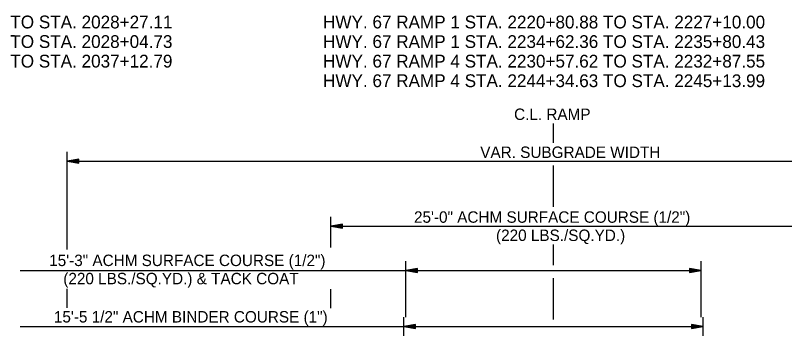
# Model space of a CAD drawing. Extents: x 1734743 to 1735935, y 759845 to 763831.
# Drawn here: x 1735729.77 to 1735769.47, y 762706.48 to 762722.65 of the extents above; entities that cross this region are included whole.
import ezdxf

# ---------------------------------------------------------------- set-up
doc = ezdxf.new("R2010")
doc.units = 0
doc.layers.add('19', color=7, linetype='Continuous')

msp = doc.modelspace()

# ---------------------------------------------------------------- linework, layer by layer
at = {"layer": '19'}
for p, q in [((1735757.547, 762716.063), (1735757.548, 762717.071)), ((1735732.446, 762710.573), (1735732.446, 762715.61)), ((1735733.046, 762715.23), (1735732.446, 762715.125)), ((1735732.446, 762715.125), (1735782.728, 762715.125)), ((1735732.446, 762715.125), (1735733.046, 762715.02)), ((1735733.046, 762715.175), (1735732.606, 762715.14)), ((1735732.606, 762715.11), (1735733.046, 762715.07)), ((1735733.046, 762715.02), (1735733.046, 762715.23)), ((1735757.548, 762712.763), (1735757.548, 762714.901)), ((1735746.047, 762710.67), (1735746.047, 762712.254)), ((1735746.647, 762711.874), (1735746.047, 762711.769)), ((1735746.647, 762711.819), (1735746.207, 762711.784)), ((1735746.647, 762711.664), (1735746.647, 762711.874)), ((1735746.047, 762711.769), (1735771.046, 762711.769)), ((1735746.047, 762711.769), (1735746.647, 762711.664)), ((1735746.207, 762711.754), (1735746.647, 762711.714)), ((1735757.548, 762709.759), (1735757.548, 762710.828)), ((1735749.92, 762707.074), (1735749.92, 762709.964)), ((1735765.165, 762707.074), (1735765.165, 762709.964)), ((1735730.014, 762709.479), (1735749.814, 762709.479)), ((1735749.811, 762709.479), (1735765.165, 762709.479)), ((1735750.52, 762709.584), (1735749.92, 762709.479)), ((1735749.92, 762709.479), (1735750.52, 762709.374)), ((1735750.52, 762709.529), (1735750.08, 762709.494)), ((1735750.08, 762709.464), (1735750.52, 762709.424)), ((1735750.52, 762709.374), (1735750.52, 762709.584)), ((1735764.565, 762709.584), (1735764.565, 762709.374)), ((1735765.165, 762709.479), (1735764.565, 762709.584)), ((1735765.005, 762709.494), (1735764.565, 762709.529)), ((1735764.565, 762709.374), (1735765.165, 762709.479)), ((1735764.565, 762709.424), (1735765.005, 762709.464)), ((1735757.548, 762706.946), (1735757.548, 762709.084)), ((1735732.446, 762707.549), (1735732.446, 762708.536)), ((1735746.047, 762707.532), (1735746.047, 762708.515)), ((1735749.814, 762704.185), (1735749.814, 762707.074)), ((1735765.269, 762704.185), (1735765.269, 762707.074)), ((1735750.414, 762706.694), (1735749.814, 762706.589)), ((1735750.414, 762706.484), (1735750.414, 762706.694)), ((1735764.669, 762706.694), (1735764.669, 762706.484)), ((1735765.269, 762706.589), (1735764.669, 762706.694)), ((1735730.014, 762706.589), (1735749.814, 762706.589)), ((1735749.811, 762706.589), (1735765.269, 762706.589)), ((1735749.814, 762706.589), (1735750.414, 762706.484)), ((1735750.414, 762706.639), (1735749.974, 762706.604)), ((1735749.974, 762706.574), (1735750.414, 762706.534)), ((1735765.109, 762706.604), (1735764.669, 762706.639)), ((1735764.669, 762706.484), (1735765.269, 762706.589)), ((1735764.669, 762706.534), (1735765.109, 762706.574))]:
    msp.add_line(p, q, dxfattribs=at)

# ---------------------------------------------------------------- texts
for s, height, p in [('HWY. 62 RAMP 2 STA. 2027+97.04 TO STA. 2028+27.11', 0.65999, (1735715.064, 762721.978)), ('HWY. 67 RAMP 1 STA. 2220+80.88 TO STA. 2227+10.00', 0.65999, (1735745.648, 762721.976)), ('HWY. 62 RAMP 3 STA. 2027+74.93 TO STA. 2028+04.73', 0.65999, (1735715.064, 762720.968)), ('HWY. 67 RAMP 1 STA. 2234+62.36 TO STA. 2235+80.43', 0.65999, (1735745.648, 762720.966)), ('HWY. 62 RAMP 3 STA. 2036+67.23 TO STA. 2037+12.79', 0.65999, (1735715.063, 762719.958)), ('HWY. 67 RAMP 4 STA. 2230+57.62 TO STA. 2232+87.55', 0.65999, (1735745.648, 762719.956)), ('HWY. 67 RAMP 4 STA. 2244+34.63 TO STA. 2245+13.99', 0.65999, (1735745.648, 762718.946)), ('C.L. RAMP', 0.59, (1735755.506, 762717.25)), ('VAR. SUBGRADE WIDTH', 0.59001, (1735753.761, 762715.289)), ('25\'-0" ACHM SURFACE COURSE (1/2")', 0.59001, (1735750.342, 762711.945)), ('(220 LBS./SQ.YD.)', 0.59001, (1735754.574, 762711.004)), ('15\'-3" ACHM SURFACE COURSE (1/2")', 0.59001, (1735731.517, 762709.71)), ('(220 LBS./SQ.YD.) & TACK COAT', 0.59001, (1735732.244, 762708.77)), ('15\'-5 1/2" ACHM BINDER COURSE (1")', 0.59001, (1735731.759, 762706.797))]:
    msp.add_text(s, height=height, rotation=359.9954, dxfattribs=at).set_placement(p)

doc.saveas('drawing.dxf')
